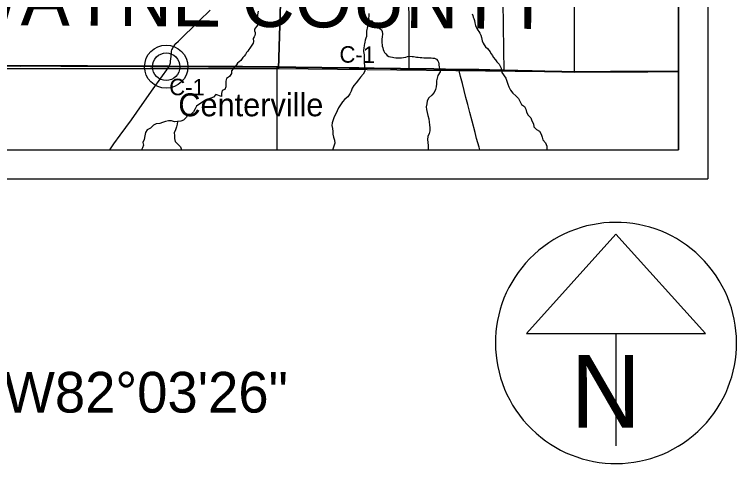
# Model space of a CAD drawing. Extents: x 0 to 34, y 0 to 22.
# Drawn here: x 6.615 to 9.099, y 13.02 to 14.565 of the extents above; entities that cross this region are included whole.
import ezdxf

# ---------------------------------------------------------------- set-up
doc = ezdxf.new("R2010")
doc.units = 0
for name, color, linetype in [('Default', 7, 'Continuous'), ('GM_X_County_Road', 7, 'Continuous'), ('GM_X_County_Road_Text', 7, 'Continuous'), ('GM_X_County_Text', 7, 'Continuous'), ('GM_X_Minor_River', 7, 'Continuous'), ('GM_X_Section', 7, 'Continuous'), ('GM_X_State_Route', 7, 'Continuous'), ('GM_X_Township_Road', 7, 'Continuous'), ('GM_X_Unincorporated', 7, 'Continuous'), ('GM_X_Unincorporated_Location', 7, 'Continuous'), ('GM_X_Unincorporated_Text', 7, 'Continuous'), ('SH_Cut_Line', 7, 'Continuous'), ('SH_Data', 7, 'Continuous'), ('SH_Text', 7, 'Continuous')]:
    doc.layers.add(name, color=color, linetype=linetype)

msp = doc.modelspace()

# ---------------------------------------------------------------- linework, layer by layer
at = {"layer": 'Default'}
for points in [[(6.5754, 14.3887), (6.6344, 14.3885), (6.681, 14.3886), (6.7058, 14.3885), (6.7369, 14.3886), (6.7742, 14.3882), (6.827, 14.388), (6.8667, 14.388), (6.8917, 14.3878), (6.9296, 14.3878), (6.994, 14.3875), (7.0321, 14.3876), (7.0818, 14.3872), (7.1469, 14.3869), (7.1734, 14.3865), (7.1982, 14.3865), (7.22, 14.3865), (7.2511, 14.3864), (7.2821, 14.3861), (7.3038, 14.3859), (7.3224, 14.3859), (7.3533, 14.3858), (7.3657, 14.3858), (7.3812, 14.3858), (7.3998, 14.3857), (7.4185, 14.3856), (7.4463, 14.3854), (7.4587, 14.3854), (7.4836, 14.3853), (7.5188, 14.385), (7.5209, 14.385), (7.5706, 14.3842), (7.583, 14.384), (7.6233, 14.3834), (7.6729, 14.3825), (7.7133, 14.3821), (7.7381, 14.3818), (7.766, 14.3816), (7.8002, 14.3814), (7.853, 14.3807), (7.9089, 14.3797), (7.9431, 14.3791), (7.9711, 14.3787), (7.9731, 14.3787), (8.0176, 14.3784), (8.0331, 14.3782), (8.058, 14.3779), (8.0828, 14.3771), (8.0983, 14.3767), (8.1169, 14.3765), (8.1355, 14.3764), (8.1436, 14.3763), (8.1479, 14.3763), (8.1572, 14.3763), (8.1882, 14.376), (8.2131, 14.3754), (8.2504, 14.3744), (8.2998, 14.3732), (8.3187, 14.3727), (8.3466, 14.3722), (8.3714, 14.3718), (8.3962, 14.3711), (8.4394, 14.3699), (8.4702, 14.3693), (8.4979, 14.3687), (8.5381, 14.3682), (8.5566, 14.3681), (8.6094, 14.3683), (8.628, 14.3683), (8.6496, 14.3684), (8.6651, 14.3685), (8.7085, 14.3685), (8.74, 14.3687), (8.7725, 14.3687), (8.7943, 14.3686), (8.8378, 14.369), (8.8533, 14.3693), (8.8688, 14.3695), (8.8904, 14.3696), (8.9, 14.3696), (8.9, 18.4271)], [(3.6803, 14.1), (8.9, 14.1), (8.9, 14.3696), (8.8904, 14.3696), (8.8688, 14.3695), (8.8533, 14.3693), (8.8378, 14.369), (8.7943, 14.3686), (8.7725, 14.3687), (8.74, 14.3687), (8.7085, 14.3685), (8.6651, 14.3685), (8.6496, 14.3684), (8.628, 14.3683), (8.6094, 14.3683), (8.5566, 14.3681), (8.5381, 14.3682), (8.4979, 14.3687), (8.4702, 14.3693), (8.4394, 14.3699), (8.3962, 14.3711), (8.3714, 14.3718), (8.3466, 14.3722), (8.3187, 14.3727), (8.2998, 14.3732), (8.2504, 14.3744), (8.2131, 14.3754), (8.1882, 14.376), (8.1572, 14.3763), (8.1479, 14.3763), (8.1436, 14.3763), (8.1355, 14.3764), (8.1169, 14.3765), (8.0983, 14.3767), (8.0828, 14.3771), (8.058, 14.3779), (8.0331, 14.3782), (8.0176, 14.3784), (7.9731, 14.3787), (7.9711, 14.3787), (7.9431, 14.3791), (7.9089, 14.3797), (7.853, 14.3807), (7.8002, 14.3814), (7.766, 14.3816), (7.7381, 14.3818), (7.7133, 14.3821), (7.6729, 14.3825), (7.6233, 14.3834), (7.583, 14.384), (7.5706, 14.3842), (7.5209, 14.385), (7.5188, 14.385), (7.4836, 14.3853), (7.4587, 14.3854), (7.4463, 14.3854), (7.4185, 14.3856), (7.3998, 14.3857), (7.3812, 14.3858), (7.3657, 14.3858), (7.3533, 14.3858), (7.3224, 14.3859), (7.3038, 14.3859), (7.2821, 14.3861), (7.2511, 14.3864), (7.22, 14.3865), (7.1982, 14.3865), (7.1734, 14.3865), (7.1469, 14.3869), (7.0818, 14.3872), (7.0321, 14.3876), (6.994, 14.3875), (6.9296, 14.3878), (6.8917, 14.3878), (6.8667, 14.388), (6.827, 14.388), (6.7742, 14.3882), (6.7369, 14.3886), (6.7058, 14.3885), (6.681, 14.3886), (6.6344, 14.3885), (6.5754, 14.3887)]]:
    msp.add_lwpolyline(points, dxfattribs=at)
msp.add_lwpolyline([(8.9, 14.3696), (8.9, 15.3782), (8.5395, 15.3753), (8.5402, 14.367)], close=True, dxfattribs=at)
at = {"layer": 'GM_X_County_Road'}
for points in [[(7.9733, 14.3781), (7.9733, 14.381), (7.973, 14.3971), (7.9729, 14.4062), (7.9729, 14.4121), (7.9728, 14.4511), (7.9725, 14.507), (7.9724, 14.5598), (7.9723, 14.597), (7.9724, 14.6249), (7.9724, 14.6373), (7.9728, 14.6467), (7.9736, 14.656), (7.9752, 14.6653), (7.9767, 14.6714), (7.9834, 14.6921), (8.0041, 14.7506), (8.0159, 14.7859), (8.0179, 14.7922), (8.0196, 14.7977)], [(7.1472, 14.3863), (7.1736, 14.386), (7.1984, 14.3859), (7.2202, 14.386), (7.2513, 14.3859), (7.2823, 14.3856), (7.304, 14.3854), (7.3226, 14.3853), (7.3535, 14.3853), (7.3659, 14.3853), (7.3814, 14.3853), (7.4001, 14.3851), (7.4187, 14.385), (7.4465, 14.3848), (7.459, 14.3848), (7.4838, 14.3848), (7.519, 14.3844)], [(7.519, 14.3844), (7.5211, 14.3844), (7.5708, 14.3836), (7.5832, 14.3834), (7.6235, 14.3829), (7.6731, 14.382), (7.7135, 14.3815), (7.7383, 14.3813), (7.7662, 14.3811), (7.8004, 14.3808), (7.8532, 14.3801), (7.9091, 14.3791), (7.9433, 14.3786), (7.9713, 14.3781), (7.9733, 14.3781)], [(7.9733, 14.3781), (8.0178, 14.3778), (8.0333, 14.3777), (8.0582, 14.3773), (8.0831, 14.3766), (8.0985, 14.3762), (8.1171, 14.376), (8.1357, 14.3758), (8.1438, 14.3758)], [(8.1438, 14.3758), (8.1481, 14.3758), (8.1574, 14.3757), (8.1884, 14.3754), (8.2133, 14.3749), (8.2506, 14.3739), (8.3, 14.3726)], [(8.2157, 14.1), (8.2133, 14.1086), (8.2051, 14.1386), (8.1996, 14.1596), (8.1893, 14.1986), (8.1814, 14.2286), (8.1744, 14.2557), (8.1681, 14.2797), (8.1559, 14.3279), (8.1497, 14.352), (8.146, 14.3671), (8.1438, 14.3758)], [(8.3, 14.3726), (8.3189, 14.3722), (8.3468, 14.3717), (8.3716, 14.3712), (8.3964, 14.3706), (8.4396, 14.3694), (8.4704, 14.3688), (8.4981, 14.3682), (8.5383, 14.3676), (8.5569, 14.3675), (8.6096, 14.3677), (8.6282, 14.3678), (8.6498, 14.3678), (8.6653, 14.368), (8.7088, 14.368), (8.7402, 14.3681), (8.7728, 14.3682), (8.7945, 14.3681), (8.838, 14.3685), (8.8535, 14.3687), (8.869, 14.3689), (8.8906, 14.369), (8.9, 14.369)]]:
    msp.add_lwpolyline(points, dxfattribs=at)
at = {"layer": 'GM_X_Minor_River'}
for points in [[(7.453, 14.5763), (7.4515, 14.5641), (7.4507, 14.5592), (7.4504, 14.5539)], [(7.8346, 14.5681), (7.8343, 14.5632), (7.8339, 14.5582), (7.8331, 14.5533), (7.8343, 14.5479), (7.8347, 14.5422), (7.8328, 14.5362), (7.8313, 14.5297), (7.8294, 14.5236), (7.8283, 14.5187), (7.8271, 14.5134), (7.8264, 14.508), (7.8256, 14.5016), (7.826, 14.4966)], [(8.1891, 14.5675), (8.1918, 14.5618), (8.193, 14.5561), (8.1953, 14.5512), (8.1972, 14.5447), (8.1991, 14.5363), (8.2015, 14.5276), (8.2038, 14.5215)], [(7.4504, 14.5539), (7.4508, 14.5474), (7.4512, 14.5425), (7.4523, 14.5364), (7.452, 14.5295), (7.4478, 14.5242), (7.4443, 14.5193), (7.4413, 14.5143), (7.4406, 14.5086), (7.4429, 14.5037), (7.4436, 14.4984), (7.4417, 14.4934), (7.4391, 14.4885), (7.436, 14.4828), (7.4376, 14.4721), (7.4361, 14.4664), (7.4292, 14.4558), (7.425, 14.4497), (7.4212, 14.4448), (7.4178, 14.4394), (7.4136, 14.4341), (7.4102, 14.428), (7.4053, 14.4223), (7.4011, 14.4174), (7.3942, 14.4067), (7.3885, 14.4026), (7.3828, 14.3972), (7.3786, 14.3923), (7.362, 14.3716)], [(7.8345, 14.5452), (7.8374, 14.5449), (7.845, 14.543), (7.8481, 14.5373), (7.8523, 14.532), (7.8599, 14.5266), (7.8656, 14.5213), (7.8718, 14.5175), (7.8775, 14.5122), (7.8802, 14.5061), (7.881, 14.4981), (7.8795, 14.4867), (7.8791, 14.481), (7.8791, 14.4749), (7.8791, 14.4681), (7.8795, 14.4612), (7.8803, 14.4559), (7.8818, 14.4506), (7.8838, 14.4445), (7.8857, 14.4395), (7.8884, 14.4346), (7.8922, 14.4297), (7.8976, 14.424), (7.9033, 14.4205), (7.9082, 14.4198), (7.9155, 14.4182), (7.9205, 14.4171), (7.9273, 14.4163), (7.9331, 14.4159), (7.9411, 14.4156), (7.9468, 14.4163), (7.9537, 14.4167), (7.9617, 14.4186), (7.9674, 14.4209), (7.9727, 14.422), (7.983, 14.4212), (7.988, 14.4205), (7.993, 14.419), (7.9987, 14.4182), (8.0044, 14.4182), (8.0113, 14.417), (8.0166, 14.4167), (8.0239, 14.4159), (8.0288, 14.4159), (8.0369, 14.4163), (8.0433, 14.4166), (8.0491, 14.4163), (8.0548, 14.4155), (8.0601, 14.4147), (8.067, 14.4117), (8.0716, 14.406), (8.0739, 14.401), (8.0751, 14.3957), (8.0751, 14.3904), (8.0759, 14.3851), (8.077, 14.3782), (8.0792, 14.3675)], [(8.2038, 14.5215), (8.2061, 14.5166), (8.2091, 14.5116), (8.2126, 14.5063), (8.216, 14.501), (8.2195, 14.4937), (8.2218, 14.4858), (8.2229, 14.4808), (8.2245, 14.4747), (8.2275, 14.4667), (8.2306, 14.4603), (8.2352, 14.4534), (8.2421, 14.4477), (8.2474, 14.4428), (8.2517, 14.4371), (8.2543, 14.431), (8.2597, 14.4237), (8.2624, 14.4184), (8.2697, 14.4089), (8.2746, 14.4024), (8.2827, 14.3941), (8.2861, 14.3869), (8.2896, 14.3804), (8.2921, 14.3654)], [(7.826, 14.4966), (7.8257, 14.4898), (7.8238, 14.4833), (7.8215, 14.4772), (7.8204, 14.4704), (7.8188, 14.4647), (7.8181, 14.4597), (7.8166, 14.4483), (7.8162, 14.4434), (7.8162, 14.4377), (7.817, 14.4327), (7.8178, 14.4267), (7.8182, 14.4202), (7.8182, 14.413), (7.8178, 14.4061), (7.8186, 14.3974), (7.8194, 14.3902), (7.8198, 14.3841), (7.8198, 14.3784), (7.8204, 14.3698)], [(7.362, 14.3716), (7.3619, 14.3619), (7.3547, 14.3524), (7.3449, 14.3455), (7.3416, 14.336), (7.342, 14.3262), (7.3421, 14.3163), (7.3391, 14.3068), (7.3293, 14.3033), (7.3271, 14.2938), (7.3272, 14.2832), (7.3074, 14.2899), (7.2999, 14.2804), (7.2901, 14.2777), (7.2799, 14.2734), (7.2701, 14.2696), (7.2407, 14.2501), (7.2362, 14.2402), (7.2314, 14.2303), (7.2212, 14.2207), (7.2113, 14.2207), (7.2054, 14.2112), (7.1967, 14.2016), (7.1869, 14.1985), (7.1763, 14.1973), (7.1657, 14.1965), (7.1547, 14.1991), (7.1444, 14.1994), (7.1346, 14.1967), (7.1248, 14.1936), (7.115, 14.1897), (7.1029, 14.1889), (7.0927, 14.1847), (7.0825, 14.1744), (7.0719, 14.1686), (7.0652, 14.1587), (7.0638, 14.1477), (7.0608, 14.1356), (7.0571, 14.1253), (7.0583, 14.1155), (7.0557, 14.106), (7.0515, 14.1)], [(7.8204, 14.3698), (7.8142, 14.3598), (7.8056, 14.3499), (7.7981, 14.34), (7.7909, 14.3305), (7.7823, 14.321), (7.7763, 14.3114), (7.7733, 14.3016), (7.7692, 14.2921), (7.7617, 14.2814), (7.7519, 14.2738), (7.7433, 14.2642), (7.7366, 14.2543), (7.7302, 14.2444), (7.7253, 14.2342), (7.7205, 14.2231), (7.7145, 14.2129), (7.7119, 14.203), (7.7078, 14.1927), (7.7071, 14.1832), (7.7091, 14.1734), (7.7103, 14.1628), (7.7108, 14.1533), (7.7127, 14.1431), (7.7158, 14.1329), (7.7171, 14.1226), (7.7133, 14.112), (7.7108, 14.1017), (7.7092, 14.1)], [(8.0792, 14.3675), (8.0711, 14.3558), (8.0689, 14.3459), (8.0667, 14.3364), (8.0667, 14.3265), (8.0657, 14.3163), (8.0635, 14.3068), (8.0586, 14.2973), (8.0507, 14.2878), (8.041, 14.2782), (8.035, 14.268), (8.0332, 14.2577), (8.0317, 14.2478), (8.0325, 14.238), (8.0345, 14.2278), (8.0372, 14.2172), (8.0403, 14.2066), (8.0412, 14.1952), (8.0432, 14.1853), (8.0444, 14.1755), (8.0437, 14.1653), (8.0415, 14.1558), (8.037, 14.1451), (8.0356, 14.1356), (8.0372, 14.1246), (8.0384, 14.1144), (8.0388, 14.1042), (8.0388, 14.1)], [(8.2921, 14.3654), (8.3057, 14.3459), (8.3091, 14.336), (8.3126, 14.3258), (8.3161, 14.316), (8.3219, 14.3046), (8.3299, 14.2941), (8.3394, 14.285), (8.3493, 14.276), (8.3547, 14.265), (8.359, 14.2552), (8.3692, 14.2492), (8.3742, 14.2394), (8.377, 14.2292), (8.3827, 14.219), (8.3911, 14.2092), (8.3946, 14.1989), (8.4004, 14.1891), (8.4023, 14.1789), (8.4115, 14.1691), (8.421, 14.1635), (8.4275, 14.1536), (8.4302, 14.1434), (8.4333, 14.1336), (8.4421, 14.1234), (8.446, 14.1124), (8.4468, 14.1026), (8.4467, 14.1)], [(7.1763, 14.1973), (7.1745, 14.1878), (7.1723, 14.1784), (7.1689, 14.1685), (7.1648, 14.1586), (7.1653, 14.1487), (7.1653, 14.1389), (7.1677, 14.1287), (7.1772, 14.1196), (7.1856, 14.1098), (7.1894, 14.1)]]:
    msp.add_lwpolyline(points, dxfattribs=at)
at = {"layer": 'GM_X_Section'}
for points in [[(6.508, 15.3973), (7.534, 15.3931), (7.5388, 14.869), (7.5234, 14.3784), (6.5187, 14.3786)], [(7.534, 15.3931), (8.5395, 15.3753), (8.5402, 14.367), (7.5234, 14.3784), (7.5388, 14.869)]]:
    msp.add_lwpolyline(points, close=True, dxfattribs=at)
at = {"layer": 'GM_X_State_Route'}
for points in [[(7.1472, 14.3863), (7.1486, 14.3901), (7.1495, 14.3925), (7.1504, 14.3953), (7.1512, 14.3986), (7.1518, 14.4022), (7.1523, 14.4063), (7.1528, 14.412), (7.1548, 14.4328), (7.1556, 14.4392), (7.1565, 14.4431), (7.1581, 14.4474), (7.1595, 14.4502), (7.1627, 14.4554), (7.1663, 14.4604), (7.1704, 14.465), (7.179, 14.4739), (7.2081, 14.502), (7.2193, 14.5128), (7.2503, 14.5433), (7.288, 14.5802)], [(6.5756, 14.3881), (6.6346, 14.3879), (6.6812, 14.388), (6.7061, 14.388), (6.7371, 14.3881), (6.7744, 14.3876), (6.8272, 14.3875), (6.867, 14.3874), (6.8919, 14.3873), (6.9298, 14.3872), (6.9942, 14.387), (7.0323, 14.387), (7.082, 14.3866), (7.1472, 14.3863)], [(6.9426, 14.1), (6.9569, 14.1199), (6.9789, 14.1499), (7.017, 14.2028), (7.0548, 14.2559), (7.0922, 14.3092), (7.1447, 14.3833), (7.1472, 14.3863)]]:
    msp.add_lwpolyline(points, dxfattribs=at)
at = {"layer": 'GM_X_Township_Road'}
for points in [[(8.3, 14.3726), (8.2999, 14.3753), (8.2995, 14.3846), (8.2986, 14.4314), (8.2981, 14.472), (8.2979, 14.5001), (8.2971, 14.5562), (8.2969, 14.5811), (8.2966, 14.5967), (8.2963, 14.6092), (8.296, 14.6247), (8.2961, 14.6403), (8.2959, 14.659), (8.2961, 14.6911)], [(7.5188, 14.1), (7.5186, 14.1657), (7.5188, 14.1937), (7.5185, 14.2341), (7.5191, 14.3211), (7.519, 14.3823), (7.519, 14.3844)]]:
    msp.add_lwpolyline(points, dxfattribs=at)
at = {"layer": 'GM_X_Unincorporated'}
for radius in [0.0744, 0.0472]:
    msp.add_circle((7.137, 14.3856), radius, dxfattribs=at)
at = {"layer": 'GM_X_Unincorporated_Location'}
msp.add_line((7.137, 14.3856), (7.137, 14.3856), dxfattribs=at)
at = {"layer": 'SH_Cut_Line'}
for points in [[(6.5754, 14.3887), (6.6344, 14.3885), (6.681, 14.3886), (6.7058, 14.3885), (6.7369, 14.3886), (6.7742, 14.3882), (6.827, 14.388), (6.8667, 14.388), (6.8917, 14.3878), (6.9296, 14.3878), (6.994, 14.3875), (7.0321, 14.3876), (7.0818, 14.3872), (7.1469, 14.3869), (7.1734, 14.3865), (7.1982, 14.3865), (7.22, 14.3865), (7.2511, 14.3864), (7.2821, 14.3861), (7.3038, 14.3859), (7.3224, 14.3859), (7.3533, 14.3858), (7.3657, 14.3858), (7.3812, 14.3858), (7.3998, 14.3857), (7.4185, 14.3856), (7.4463, 14.3854), (7.4587, 14.3854), (7.4836, 14.3853), (7.5188, 14.385), (7.5209, 14.385), (7.5706, 14.3842), (7.583, 14.384), (7.6233, 14.3834), (7.6729, 14.3825), (7.7133, 14.3821), (7.7381, 14.3818), (7.766, 14.3816), (7.8002, 14.3814), (7.853, 14.3807), (7.9089, 14.3797), (7.9431, 14.3791), (7.9711, 14.3787), (7.9731, 14.3787), (8.0176, 14.3784), (8.0331, 14.3782), (8.058, 14.3779), (8.0828, 14.3771), (8.0983, 14.3767), (8.1169, 14.3765), (8.1355, 14.3764), (8.1436, 14.3763), (8.1479, 14.3763), (8.1572, 14.3763), (8.1882, 14.376), (8.2131, 14.3754), (8.2504, 14.3744), (8.2998, 14.3732), (8.3187, 14.3727), (8.3466, 14.3722), (8.3714, 14.3718), (8.3962, 14.3711), (8.4394, 14.3699), (8.4702, 14.3693), (8.4979, 14.3687), (8.5381, 14.3682), (8.5566, 14.3681), (8.6094, 14.3683), (8.628, 14.3683), (8.6496, 14.3684), (8.6651, 14.3685), (8.7085, 14.3685), (8.74, 14.3687), (8.7725, 14.3687), (8.7943, 14.3686), (8.8378, 14.369), (8.8533, 14.3693), (8.8688, 14.3695), (8.8904, 14.3696), (8.9, 14.3696), (8.9, 20.9)], [(2.1, 14.1), (8.9, 14.1), (8.9, 14.3696), (8.8904, 14.3696), (8.8688, 14.3695), (8.8533, 14.3693), (8.8378, 14.369), (8.7943, 14.3686), (8.7725, 14.3687), (8.74, 14.3687), (8.7085, 14.3685), (8.6651, 14.3685), (8.6496, 14.3684), (8.628, 14.3683), (8.6094, 14.3683), (8.5566, 14.3681), (8.5381, 14.3682), (8.4979, 14.3687), (8.4702, 14.3693), (8.4394, 14.3699), (8.3962, 14.3711), (8.3714, 14.3718), (8.3466, 14.3722), (8.3187, 14.3727), (8.2998, 14.3732), (8.2504, 14.3744), (8.2131, 14.3754), (8.1882, 14.376), (8.1572, 14.3763), (8.1479, 14.3763), (8.1436, 14.3763), (8.1355, 14.3764), (8.1169, 14.3765), (8.0983, 14.3767), (8.0828, 14.3771), (8.058, 14.3779), (8.0331, 14.3782), (8.0176, 14.3784), (7.9731, 14.3787), (7.9711, 14.3787), (7.9431, 14.3791), (7.9089, 14.3797), (7.853, 14.3807), (7.8002, 14.3814), (7.766, 14.3816), (7.7381, 14.3818), (7.7133, 14.3821), (7.6729, 14.3825), (7.6233, 14.3834), (7.583, 14.384), (7.5706, 14.3842), (7.5209, 14.385), (7.5188, 14.385), (7.4836, 14.3853), (7.4587, 14.3854), (7.4463, 14.3854), (7.4185, 14.3856), (7.3998, 14.3857), (7.3812, 14.3858), (7.3657, 14.3858), (7.3533, 14.3858), (7.3224, 14.3859), (7.3038, 14.3859), (7.2821, 14.3861), (7.2511, 14.3864), (7.22, 14.3865), (7.1982, 14.3865), (7.1734, 14.3865), (7.1469, 14.3869), (7.0818, 14.3872), (7.0321, 14.3876), (6.994, 14.3875), (6.9296, 14.3878), (6.8917, 14.3878), (6.8667, 14.388), (6.827, 14.388), (6.7742, 14.3882), (6.7369, 14.3886), (6.7058, 14.3885), (6.681, 14.3886), (6.6344, 14.3885), (6.5754, 14.3887)]]:
    msp.add_lwpolyline(points, dxfattribs=at)
at = {"layer": 'SH_Data'}
for p, q in [((9, 21), (9, 14)), ((8.9, 20.9), (8.9, 14.1)), ((2.1, 14.1), (8.9, 14.1)), ((2, 14), (9, 14)), ((8.6845, 13.809), (8.3769, 13.4678)), ((8.9921, 13.4678), (8.6845, 13.809)), ((8.3769, 13.4678), (8.9921, 13.4678)), ((8.6845, 13.4678), (8.6845, 13.081)), ((8.6845, 13.4353), (8.6845, 13.4353)), ((8.6845, 13.4353), (8.6845, 13.4353))]:
    msp.add_line(p, q, dxfattribs=at)
msp.add_arc((8.6845, 13.4353), 0.4148, 129.7798, 129.7633, dxfattribs=at)

# ---------------------------------------------------------------- texts
at = {"layer": 'GM_X_County_Road_Text'}
for rotation, p in [(359.2308, (7.7328, 14.3998)), (359.5382, (7.1472, 14.2876))]:
    msp.add_text('C-1', height=0.05682, rotation=rotation, dxfattribs=at).set_placement(p)
at = {"layer": 'GM_X_County_Text'}
msp.add_text('WAYNE COUNTY', height=0.189394, rotation=359.5961, dxfattribs=at).set_placement((6.397, 14.5298))
at = {"layer": 'GM_X_Unincorporated_Text'}
msp.add_text('Centerville', height=0.078977, rotation=0, dxfattribs=at).set_placement((7.1787, 14.215))
at = {"layer": 'SH_Data'}
msp.add_text('N', height=0.25, dxfattribs=at).set_placement((8.5292, 13.1439))
at = {"layer": 'SH_Text'}
msp.add_text('LATITUDE:  N40°43\'20"     LONGITUDE:  W82°03\'26"', height=0.14, dxfattribs=at).set_placement((3.071, 13.1958))

doc.saveas('drawing.dxf')
